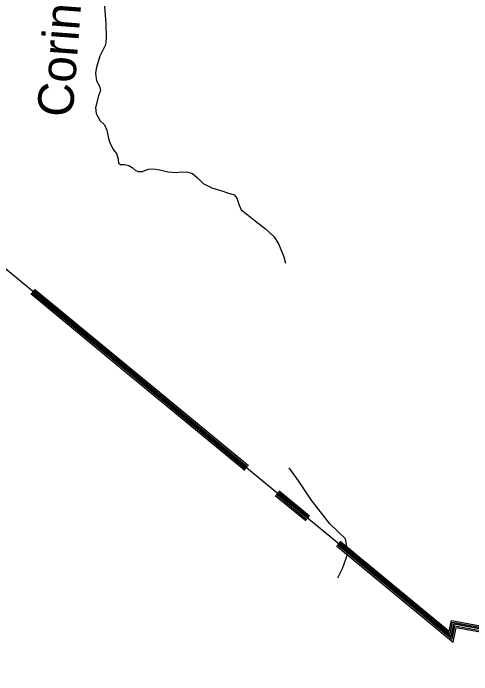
# Model space of a CAD drawing. Extents: x 1788175 to 1969470, y 584502 to 738744.
# Drawn here: x 1823147 to 1829254, y 632693 to 641514 of the extents above; entities that cross this region are included whole.
import ezdxf

# ---------------------------------------------------------------- set-up
doc = ezdxf.new("R2010")
doc.units = 0
for name, color, linetype in [('DESIGN - DRAINAGE - Bridges and Cross Drains Size Text', 7, 'Continuous'), ('DESIGN - TRANSPORTATION - Text', 7, 'Continuous'), ('SURVEY - DRAINAGE - Natural Features', 7, 'Continuous')]:
    doc.layers.add(name, color=color, linetype=linetype)

msp = doc.modelspace()

# ---------------------------------------------------------------- linework, layer by layer
at = {"layer": 'DESIGN - TRANSPORTATION - Text'}
for points in [[(1824350.7, 641769.7), (1824379.7, 641378.3), (1824386.2, 641180.4), (1824377.3, 641094.3), (1824330.5, 641005.7), (1824301.4, 640941.3), (1824270.7, 640840.9), (1824251.6, 640770.7), (1824242.4, 640710.6), (1824253.6, 640610.8), (1824296.4, 640543.4), (1824309.2, 640481.6), (1824284.1, 640413.3), (1824242.2, 640256.8), (1824251.2, 640174.9), (1824304.4, 640079.7), (1824361, 640026.5), (1824391.8, 639953), (1824413.2, 639845.3), (1824436, 639777.7), (1824481, 639694.3), (1824521.6, 639642.9), (1824542.5, 639569.2), (1824549.2, 639515.3), (1824573.4, 639495.7), (1824627.3, 639496.4), (1824685.4, 639483.2), (1824731.7, 639457.9), (1824772.1, 639422.5), (1824810.2, 639405)], [(1824810.2, 639405), (1824868.2, 639401.8), (1824945.7, 639432.9), (1825009.5, 639437.8), (1825099.5, 639425), (1825207.7, 639398.5), (1825315.6, 639392.1), (1825393.4, 639401.1), (1825471.4, 639394.2), (1825533.5, 639377.1), (1825596.1, 639322), (1825675, 639243.1), (1825791.6, 639186.8), (1825909.8, 639150.4), (1826014.1, 639115.9), (1826088.3, 639090.9), (1826126.8, 639049.5), (1826154, 638955.9), (1826180.7, 638894.3), (1826257.4, 638833.4), (1826390.5, 638727.3), (1826503.4, 638642.9), (1826620.7, 638530.6), (1826685.9, 638429.5), (1826749.9, 638266.5), (1826771, 638180.8)], [(1827602.7, 634338), (1827573.9, 634507.2), (1827364.4, 634707.1), (1827115.9, 635024.7), (1826945.8, 635277), (1826822.4, 635451.7)], [(1827471.1, 633985.4), (1827533.5, 634110.9), (1827605.5, 634321.6), (1827602.4, 634339.7)]]:
    msp.add_lwpolyline(points, dxfattribs=at)
at = {"layer": 'SURVEY - DRAINAGE - Natural Features'}
for points in [[(1829782.1, 632772), (1829830.5, 633221.2), (1829013.8, 633371), (1828979.6, 633203.5), (1824515, 636888.2), (1820759.6, 639992.6)], [(1823417.6, 637821.4), (1824527.7, 636903.6), (1826267.4, 635467.9)], [(1823429.7, 637836), (1824539.8, 636918.3), (1826279.5, 635482.5)], [(1823379.4, 637775.1), (1824489.5, 636857.4), (1826229.2, 635421.6)], [(1823392.1, 637790.5), (1824502.3, 636872.8), (1826241.9, 635437)], [(1823404.9, 637805.9), (1824515, 636888.2), (1826254.7, 635452.4)], [(1826636.4, 635085.5), (1827043.6, 634749.4)], [(1826649.1, 635100.9), (1827056.4, 634764.8)], [(1826661.9, 635116.3), (1827069.1, 634780.3)], [(1826674.6, 635131.8), (1827081.8, 634795.7)], [(1826686.7, 635146.4), (1827093.9, 634810.3)], [(1827501.1, 634474.2), (1828954.4, 633274.9), (1828983.2, 633416.3), (1829873.2, 633253), (1829820.9, 632767.9)], [(1827450.9, 634413.3), (1829005.5, 633130.2), (1829045.1, 633324.6), (1829786.8, 633188.5), (1829733.4, 632693.3)], [(1827463.6, 634428.7), (1828992.6, 633166.9), (1829029.4, 633347.8), (1829808.6, 633204.8), (1829754.1, 632698.7)], [(1827476.3, 634444.2), (1828979.6, 633203.5), (1829013.8, 633371), (1829830.5, 633221.2), (1829782.1, 632772)], [(1827489.1, 634459.6), (1828966.7, 633240.1), (1828998.1, 633394.2), (1829852.4, 633237.5), (1829802, 632769.9)]]:
    msp.add_lwpolyline(points, dxfattribs=at)

# ---------------------------------------------------------------- texts
at = {"layer": 'DESIGN - DRAINAGE - Bridges and Cross Drains Size Text'}
msp.add_text('Corinth', height=475, rotation=85.65334, dxfattribs=at).set_placement((1823936, 640117.6))

doc.saveas('drawing.dxf')
